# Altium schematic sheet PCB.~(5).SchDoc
size A2
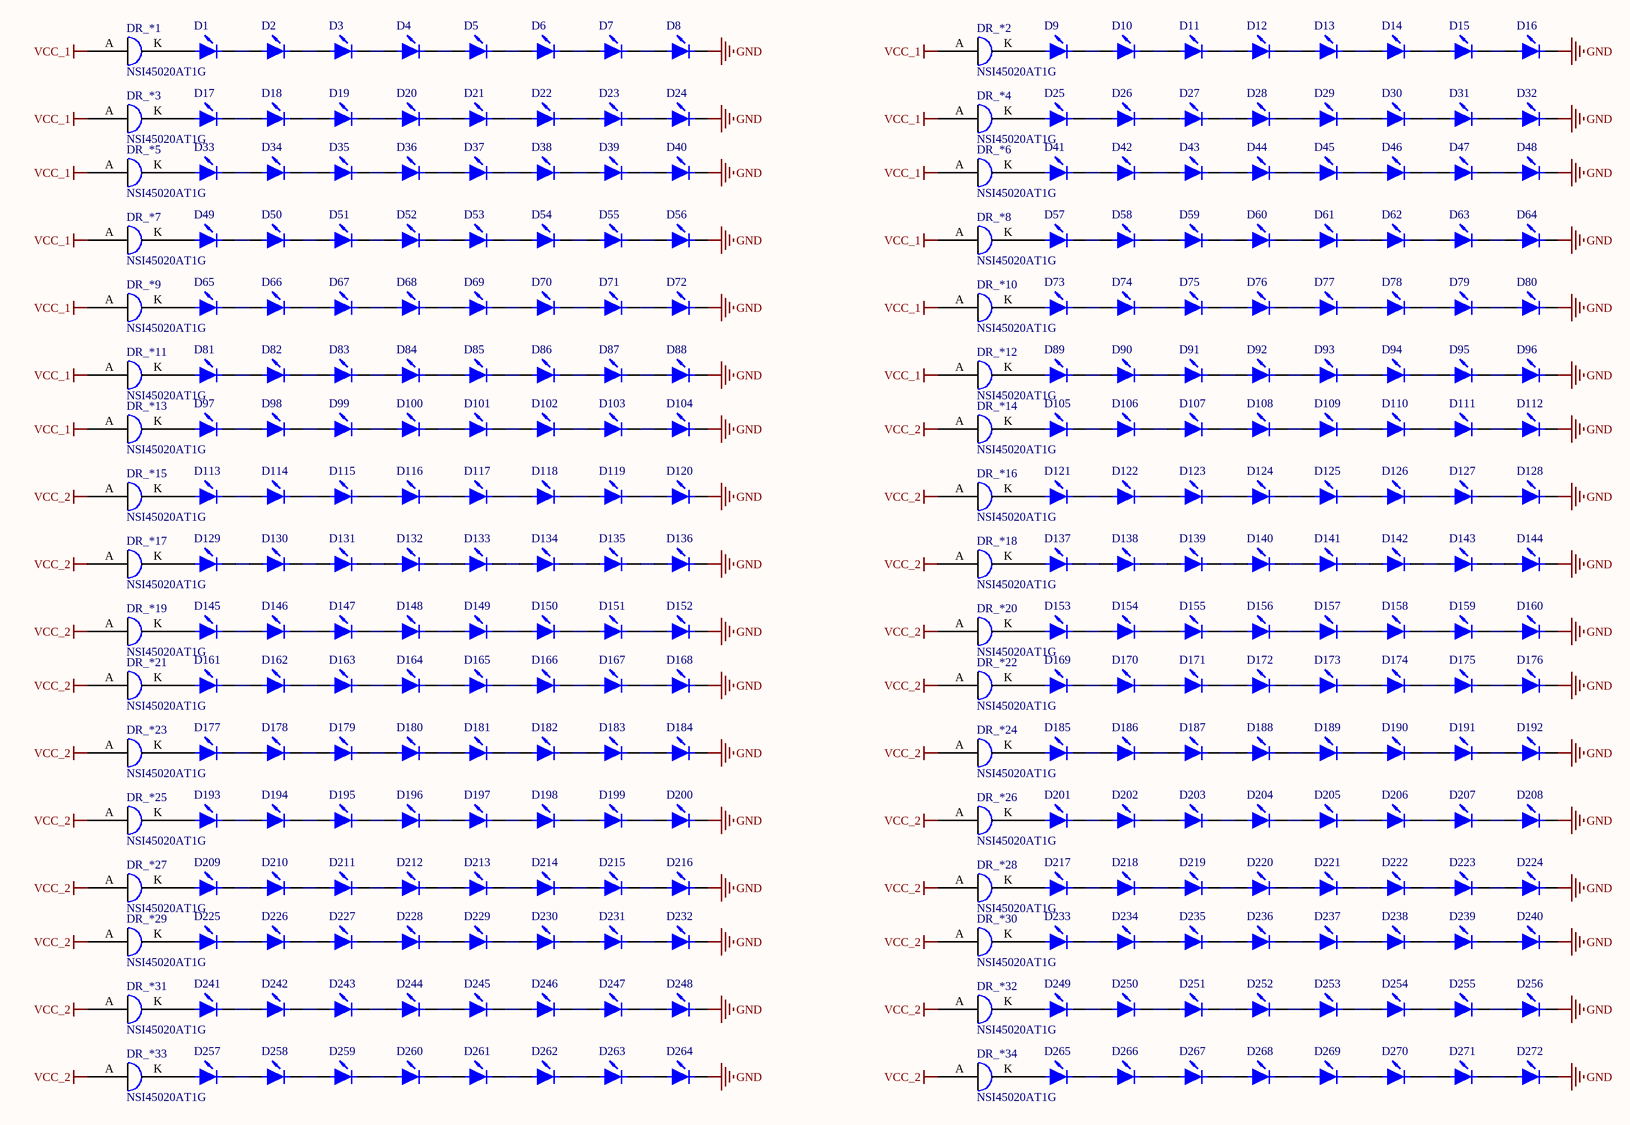
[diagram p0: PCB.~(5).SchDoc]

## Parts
D1  LED0  [UV_LED]  (value not drawn)
D2  LED0  [UV_LED]  (value not drawn)
D3  LED0  [UV_LED]  (value not drawn)
D4  LED0  [UV_LED]  (value not drawn)
D5  LED0  [UV_LED]  (value not drawn)
D6  LED0  [UV_LED]  (value not drawn)
D7  LED0  [UV_LED]  (value not drawn)
D8  LED0  [UV_LED]  (value not drawn)
D9  LED0  [UV_LED]  (value not drawn)
D10  LED0  [UV_LED]  (value not drawn)
D11  LED0  [UV_LED]  (value not drawn)
D12  LED0  [UV_LED]  (value not drawn)
D13  LED0  [UV_LED]  (value not drawn)
D14  LED0  [UV_LED]  (value not drawn)
D15  LED0  [UV_LED]  (value not drawn)
D16  LED0  [UV_LED]  (value not drawn)
D17  LED0  [UV_LED]  (value not drawn)
D18  LED0  [UV_LED]  (value not drawn)
D19  LED0  [UV_LED]  (value not drawn)
D20  LED0  [UV_LED]  (value not drawn)
D21  LED0  [UV_LED]  (value not drawn)
D22  LED0  [UV_LED]  (value not drawn)
D23  LED0  [UV_LED]  (value not drawn)
D24  LED0  [UV_LED]  (value not drawn)
D25  LED0  [UV_LED]  (value not drawn)
D26  LED0  [UV_LED]  (value not drawn)
D27  LED0  [UV_LED]  (value not drawn)
D28  LED0  [UV_LED]  (value not drawn)
D29  LED0  [UV_LED]  (value not drawn)
D30  LED0  [UV_LED]  (value not drawn)
D31  LED0  [UV_LED]  (value not drawn)
D32  LED0  [UV_LED]  (value not drawn)
D33  LED0  [UV_LED]  (value not drawn)
D34  LED0  [UV_LED]  (value not drawn)
D35  LED0  [UV_LED]  (value not drawn)
D36  LED0  [UV_LED]  (value not drawn)
D37  LED0  [UV_LED]  (value not drawn)
D38  LED0  [UV_LED]  (value not drawn)
D39  LED0  [UV_LED]  (value not drawn)
D40  LED0  [UV_LED]  (value not drawn)
D41  LED0  [UV_LED]  (value not drawn)
D42  LED0  [UV_LED]  (value not drawn)
D43  LED0  [UV_LED]  (value not drawn)
D44  LED0  [UV_LED]  (value not drawn)
D45  LED0  [UV_LED]  (value not drawn)
D46  LED0  [UV_LED]  (value not drawn)
D47  LED0  [UV_LED]  (value not drawn)
D48  LED0  [UV_LED]  (value not drawn)
D49  LED0  [UV_LED]  (value not drawn)
D50  LED0  [UV_LED]  (value not drawn)
D51  LED0  [UV_LED]  (value not drawn)
D52  LED0  [UV_LED]  (value not drawn)
D53  LED0  [UV_LED]  (value not drawn)
D54  LED0  [UV_LED]  (value not drawn)
D55  LED0  [UV_LED]  (value not drawn)
D56  LED0  [UV_LED]  (value not drawn)
D57  LED0  [UV_LED]  (value not drawn)
D58  LED0  [UV_LED]  (value not drawn)
D59  LED0  [UV_LED]  (value not drawn)
D60  LED0  [UV_LED]  (value not drawn)
D61  LED0  [UV_LED]  (value not drawn)
D62  LED0  [UV_LED]  (value not drawn)
D63  LED0  [UV_LED]  (value not drawn)
D64  LED0  [UV_LED]  (value not drawn)
D65  LED0  [UV_LED]  (value not drawn)
D66  LED0  [UV_LED]  (value not drawn)
D67  LED0  [UV_LED]  (value not drawn)
D68  LED0  [UV_LED]  (value not drawn)
D69  LED0  [UV_LED]  (value not drawn)
D70  LED0  [UV_LED]  (value not drawn)
D71  LED0  [UV_LED]  (value not drawn)
D72  LED0  [UV_LED]  (value not drawn)
D73  LED0  [UV_LED]  (value not drawn)
D74  LED0  [UV_LED]  (value not drawn)
D75  LED0  [UV_LED]  (value not drawn)
D76  LED0  [UV_LED]  (value not drawn)
D77  LED0  [UV_LED]  (value not drawn)
D78  LED0  [UV_LED]  (value not drawn)
D79  LED0  [UV_LED]  (value not drawn)
D80  LED0  [UV_LED]  (value not drawn)
D81  LED0  [UV_LED]  (value not drawn)
D82  LED0  [UV_LED]  (value not drawn)
D83  LED0  [UV_LED]  (value not drawn)
D84  LED0  [UV_LED]  (value not drawn)
D85  LED0  [UV_LED]  (value not drawn)
D86  LED0  [UV_LED]  (value not drawn)
D87  LED0  [UV_LED]  (value not drawn)
D88  LED0  [UV_LED]  (value not drawn)
D89  LED0  [UV_LED]  (value not drawn)
D90  LED0  [UV_LED]  (value not drawn)
D91  LED0  [UV_LED]  (value not drawn)
D92  LED0  [UV_LED]  (value not drawn)
D93  LED0  [UV_LED]  (value not drawn)
D94  LED0  [UV_LED]  (value not drawn)
D95  LED0  [UV_LED]  (value not drawn)
D96  LED0  [UV_LED]  (value not drawn)
D97  LED0  [UV_LED]  (value not drawn)
D98  LED0  [UV_LED]  (value not drawn)
D99  LED0  [UV_LED]  (value not drawn)
D100  LED0  [UV_LED]  (value not drawn)
D101  LED0  [UV_LED]  (value not drawn)
D102  LED0  [UV_LED]  (value not drawn)
D103  LED0  [UV_LED]  (value not drawn)
D104  LED0  [UV_LED]  (value not drawn)
D105  LED0  [UV_LED]  (value not drawn)
D106  LED0  [UV_LED]  (value not drawn)
D107  LED0  [UV_LED]  (value not drawn)
D108  LED0  [UV_LED]  (value not drawn)
D109  LED0  [UV_LED]  (value not drawn)
D110  LED0  [UV_LED]  (value not drawn)
D111  LED0  [UV_LED]  (value not drawn)
D112  LED0  [UV_LED]  (value not drawn)
D113  LED0  [UV_LED]  (value not drawn)
D114  LED0  [UV_LED]  (value not drawn)
D115  LED0  [UV_LED]  (value not drawn)
D116  LED0  [UV_LED]  (value not drawn)
D117  LED0  [UV_LED]  (value not drawn)
D118  LED0  [UV_LED]  (value not drawn)
D119  LED0  [UV_LED]  (value not drawn)
D120  LED0  [UV_LED]  (value not drawn)
D121  LED0  [UV_LED]  (value not drawn)
D122  LED0  [UV_LED]  (value not drawn)
D123  LED0  [UV_LED]  (value not drawn)
D124  LED0  [UV_LED]  (value not drawn)
D125  LED0  [UV_LED]  (value not drawn)
D126  LED0  [UV_LED]  (value not drawn)
D127  LED0  [UV_LED]  (value not drawn)
D128  LED0  [UV_LED]  (value not drawn)
D129  LED0  [UV_LED]  (value not drawn)
D130  LED0  [UV_LED]  (value not drawn)
D131  LED0  [UV_LED]  (value not drawn)
D132  LED0  [UV_LED]  (value not drawn)
D133  LED0  [UV_LED]  (value not drawn)
D134  LED0  [UV_LED]  (value not drawn)
D135  LED0  [UV_LED]  (value not drawn)
D136  LED0  [UV_LED]  (value not drawn)
D137  LED0  [UV_LED]  (value not drawn)
D138  LED0  [UV_LED]  (value not drawn)
D139  LED0  [UV_LED]  (value not drawn)
D140  LED0  [UV_LED]  (value not drawn)
D141  LED0  [UV_LED]  (value not drawn)
D142  LED0  [UV_LED]  (value not drawn)
D143  LED0  [UV_LED]  (value not drawn)
D144  LED0  [UV_LED]  (value not drawn)
D145  LED0  [UV_LED]  (value not drawn)
D146  LED0  [UV_LED]  (value not drawn)
D147  LED0  [UV_LED]  (value not drawn)
D148  LED0  [UV_LED]  (value not drawn)
D149  LED0  [UV_LED]  (value not drawn)
D150  LED0  [UV_LED]  (value not drawn)
D151  LED0  [UV_LED]  (value not drawn)
D152  LED0  [UV_LED]  (value not drawn)
D153  LED0  [UV_LED]  (value not drawn)
D154  LED0  [UV_LED]  (value not drawn)
D155  LED0  [UV_LED]  (value not drawn)
D156  LED0  [UV_LED]  (value not drawn)
D157  LED0  [UV_LED]  (value not drawn)
D158  LED0  [UV_LED]  (value not drawn)
D159  LED0  [UV_LED]  (value not drawn)
D160  LED0  [UV_LED]  (value not drawn)
D161  LED0  [UV_LED]  (value not drawn)
D162  LED0  [UV_LED]  (value not drawn)
D163  LED0  [UV_LED]  (value not drawn)
D164  LED0  [UV_LED]  (value not drawn)
D165  LED0  [UV_LED]  (value not drawn)
D166  LED0  [UV_LED]  (value not drawn)
D167  LED0  [UV_LED]  (value not drawn)
D168  LED0  [UV_LED]  (value not drawn)
D169  LED0  [UV_LED]  (value not drawn)
D170  LED0  [UV_LED]  (value not drawn)
D171  LED0  [UV_LED]  (value not drawn)
D172  LED0  [UV_LED]  (value not drawn)
D173  LED0  [UV_LED]  (value not drawn)
D174  LED0  [UV_LED]  (value not drawn)
D175  LED0  [UV_LED]  (value not drawn)
D176  LED0  [UV_LED]  (value not drawn)
D177  LED0  [UV_LED]  (value not drawn)
D178  LED0  [UV_LED]  (value not drawn)
D179  LED0  [UV_LED]  (value not drawn)
D180  LED0  [UV_LED]  (value not drawn)
D181  LED0  [UV_LED]  (value not drawn)
D182  LED0  [UV_LED]  (value not drawn)
D183  LED0  [UV_LED]  (value not drawn)
D184  LED0  [UV_LED]  (value not drawn)
D185  LED0  [UV_LED]  (value not drawn)
D186  LED0  [UV_LED]  (value not drawn)
D187  LED0  [UV_LED]  (value not drawn)
D188  LED0  [UV_LED]  (value not drawn)
D189  LED0  [UV_LED]  (value not drawn)
D190  LED0  [UV_LED]  (value not drawn)
D191  LED0  [UV_LED]  (value not drawn)
D192  LED0  [UV_LED]  (value not drawn)
D193  LED0  [UV_LED]  (value not drawn)
D194  LED0  [UV_LED]  (value not drawn)
D195  LED0  [UV_LED]  (value not drawn)
D196  LED0  [UV_LED]  (value not drawn)
D197  LED0  [UV_LED]  (value not drawn)
D198  LED0  [UV_LED]  (value not drawn)
D199  LED0  [UV_LED]  (value not drawn)
D200  LED0  [UV_LED]  (value not drawn)
D201  LED0  [UV_LED]  (value not drawn)
D202  LED0  [UV_LED]  (value not drawn)
D203  LED0  [UV_LED]  (value not drawn)
D204  LED0  [UV_LED]  (value not drawn)
D205  LED0  [UV_LED]  (value not drawn)
D206  LED0  [UV_LED]  (value not drawn)
D207  LED0  [UV_LED]  (value not drawn)
D208  LED0  [UV_LED]  (value not drawn)
D209  LED0  [UV_LED]  (value not drawn)
D210  LED0  [UV_LED]  (value not drawn)
D211  LED0  [UV_LED]  (value not drawn)
D212  LED0  [UV_LED]  (value not drawn)
D213  LED0  [UV_LED]  (value not drawn)
D214  LED0  [UV_LED]  (value not drawn)
D215  LED0  [UV_LED]  (value not drawn)
D216  LED0  [UV_LED]  (value not drawn)
D217  LED0  [UV_LED]  (value not drawn)
D218  LED0  [UV_LED]  (value not drawn)
D219  LED0  [UV_LED]  (value not drawn)
D220  LED0  [UV_LED]  (value not drawn)
D221  LED0  [UV_LED]  (value not drawn)
D222  LED0  [UV_LED]  (value not drawn)
D223  LED0  [UV_LED]  (value not drawn)
D224  LED0  [UV_LED]  (value not drawn)
D225  LED0  [UV_LED]  (value not drawn)
D226  LED0  [UV_LED]  (value not drawn)
D227  LED0  [UV_LED]  (value not drawn)
D228  LED0  [UV_LED]  (value not drawn)
D229  LED0  [UV_LED]  (value not drawn)
D230  LED0  [UV_LED]  (value not drawn)
D231  LED0  [UV_LED]  (value not drawn)
D232  LED0  [UV_LED]  (value not drawn)
D233  LED0  [UV_LED]  (value not drawn)
D234  LED0  [UV_LED]  (value not drawn)
D235  LED0  [UV_LED]  (value not drawn)
D236  LED0  [UV_LED]  (value not drawn)
D237  LED0  [UV_LED]  (value not drawn)
D238  LED0  [UV_LED]  (value not drawn)
D239  LED0  [UV_LED]  (value not drawn)
D240  LED0  [UV_LED]  (value not drawn)
D241  LED0  [UV_LED]  (value not drawn)
D242  LED0  [UV_LED]  (value not drawn)
D243  LED0  [UV_LED]  (value not drawn)
D244  LED0  [UV_LED]  (value not drawn)
D245  LED0  [UV_LED]  (value not drawn)
D246  LED0  [UV_LED]  (value not drawn)
D247  LED0  [UV_LED]  (value not drawn)
D248  LED0  [UV_LED]  (value not drawn)
D249  LED0  [UV_LED]  (value not drawn)
D250  LED0  [UV_LED]  (value not drawn)
D251  LED0  [UV_LED]  (value not drawn)
D252  LED0  [UV_LED]  (value not drawn)
D253  LED0  [UV_LED]  (value not drawn)
D254  LED0  [UV_LED]  (value not drawn)
D255  LED0  [UV_LED]  (value not drawn)
D256  LED0  [UV_LED]  (value not drawn)
D257  LED0  [UV_LED]  (value not drawn)
D258  LED0  [UV_LED]  (value not drawn)
D259  LED0  [UV_LED]  (value not drawn)
D260  LED0  [UV_LED]  (value not drawn)
D261  LED0  [UV_LED]  (value not drawn)
D262  LED0  [UV_LED]  (value not drawn)
D263  LED0  [UV_LED]  (value not drawn)
D264  LED0  [UV_LED]  (value not drawn)
D265  LED0  [UV_LED]  (value not drawn)
D266  LED0  [UV_LED]  (value not drawn)
D267  LED0  [UV_LED]  (value not drawn)
D268  LED0  [UV_LED]  (value not drawn)
D269  LED0  [UV_LED]  (value not drawn)
D270  LED0  [UV_LED]  (value not drawn)
D271  LED0  [UV_LED]  (value not drawn)
D272  LED0  [UV_LED]  (value not drawn)
DR_*1  NSI45020AT1G  [NSI45020AT1G]
DR_*2  NSI45020AT1G  [NSI45020AT1G]
DR_*3  NSI45020AT1G  [NSI45020AT1G]
DR_*4  NSI45020AT1G  [NSI45020AT1G]
DR_*5  NSI45020AT1G  [NSI45020AT1G]
DR_*6  NSI45020AT1G  [NSI45020AT1G]
DR_*7  NSI45020AT1G  [NSI45020AT1G]
DR_*8  NSI45020AT1G  [NSI45020AT1G]
DR_*9  NSI45020AT1G  [NSI45020AT1G]
DR_*10  NSI45020AT1G  [NSI45020AT1G]
DR_*11  NSI45020AT1G  [NSI45020AT1G]
DR_*12  NSI45020AT1G  [NSI45020AT1G]
DR_*13  NSI45020AT1G  [NSI45020AT1G]
DR_*14  NSI45020AT1G  [NSI45020AT1G]
DR_*15  NSI45020AT1G  [NSI45020AT1G]
DR_*16  NSI45020AT1G  [NSI45020AT1G]
DR_*17  NSI45020AT1G  [NSI45020AT1G]
DR_*18  NSI45020AT1G  [NSI45020AT1G]
DR_*19  NSI45020AT1G  [NSI45020AT1G]
DR_*20  NSI45020AT1G  [NSI45020AT1G]
DR_*21  NSI45020AT1G  [NSI45020AT1G]
DR_*22  NSI45020AT1G  [NSI45020AT1G]
DR_*23  NSI45020AT1G  [NSI45020AT1G]
DR_*24  NSI45020AT1G  [NSI45020AT1G]
DR_*25  NSI45020AT1G  [NSI45020AT1G]
DR_*26  NSI45020AT1G  [NSI45020AT1G]
DR_*27  NSI45020AT1G  [NSI45020AT1G]
DR_*28  NSI45020AT1G  [NSI45020AT1G]
DR_*29  NSI45020AT1G  [NSI45020AT1G]
DR_*30  NSI45020AT1G  [NSI45020AT1G]
DR_*31  NSI45020AT1G  [NSI45020AT1G]
DR_*32  NSI45020AT1G  [NSI45020AT1G]
DR_*33  NSI45020AT1G  [NSI45020AT1G]
DR_*34  NSI45020AT1G  [NSI45020AT1G]

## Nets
GND: D8.2(K) D16.2(K) D24.2(K) D32.2(K) D40.2(K) D48.2(K) D56.2(K) D64.2(K) D72.2(K) D80.2(K) D88.2(K) D96.2(K) D104.2(K) D112.2(K) D120.2(K) D128.2(K) D136.2(K) D144.2(K) D152.2(K) D160.2(K) D168.2(K) D176.2(K) D184.2(K) D192.2(K) D200.2(K) D208.2(K) D216.2(K) D224.2(K) D232.2(K) D240.2(K) D248.2(K) D256.2(K) D264.2(K) D272.2(K)
VCC_1: DR_*1.A DR_*2.A DR_*3.A DR_*4.A DR_*5.A DR_*6.A DR_*7.A DR_*8.A DR_*9.A DR_*10.A DR_*11.A DR_*12.A DR_*13.A
VCC_2: DR_*14.A DR_*15.A DR_*16.A DR_*17.A DR_*18.A DR_*19.A DR_*20.A DR_*21.A DR_*22.A DR_*23.A DR_*24.A DR_*25.A DR_*26.A DR_*27.A DR_*28.A DR_*29.A DR_*30.A DR_*31.A DR_*32.A DR_*33.A DR_*34.A
NetD1_1: D1.1(A) DR_*1.K
NetD1_2: D1.2(K) D2.1(A)
NetD2_2: D2.2(K) D3.1(A)
NetD3_2: D3.2(K) D4.1(A)
NetD4_2: D4.2(K) D5.1(A)
NetD5_2: D5.2(K) D6.1(A)
NetD6_2: D6.2(K) D7.1(A)
NetD7_2: D7.2(K) D8.1(A)
NetD9_1: D9.1(A) DR_*2.K
NetD9_2: D9.2(K) D10.1(A)
NetD10_2: D10.2(K) D11.1(A)
NetD11_2: D11.2(K) D12.1(A)
NetD12_2: D12.2(K) D13.1(A)
NetD13_2: D13.2(K) D14.1(A)
NetD14_2: D14.2(K) D15.1(A)
NetD15_2: D15.2(K) D16.1(A)
NetD17_1: D17.1(A) DR_*3.K
NetD17_2: D17.2(K) D18.1(A)
NetD18_2: D18.2(K) D19.1(A)
NetD19_2: D19.2(K) D20.1(A)
NetD20_2: D20.2(K) D21.1(A)
NetD21_2: D21.2(K) D22.1(A)
NetD22_2: D22.2(K) D23.1(A)
NetD23_2: D23.2(K) D24.1(A)
NetD25_1: D25.1(A) DR_*4.K
NetD25_2: D25.2(K) D26.1(A)
NetD26_2: D26.2(K) D27.1(A)
NetD27_2: D27.2(K) D28.1(A)
NetD28_2: D28.2(K) D29.1(A)
NetD29_2: D29.2(K) D30.1(A)
NetD30_2: D30.2(K) D31.1(A)
NetD31_2: D31.2(K) D32.1(A)
NetD33_1: D33.1(A) DR_*5.K
NetD33_2: D33.2(K) D34.1(A)
NetD34_2: D34.2(K) D35.1(A)
NetD35_2: D35.2(K) D36.1(A)
NetD36_2: D36.2(K) D37.1(A)
NetD37_2: D37.2(K) D38.1(A)
NetD38_2: D38.2(K) D39.1(A)
NetD39_2: D39.2(K) D40.1(A)
NetD41_1: D41.1(A) DR_*6.K
NetD41_2: D41.2(K) D42.1(A)
NetD42_2: D42.2(K) D43.1(A)
NetD43_2: D43.2(K) D44.1(A)
NetD44_2: D44.2(K) D45.1(A)
NetD45_2: D45.2(K) D46.1(A)
NetD46_2: D46.2(K) D47.1(A)
NetD47_2: D47.2(K) D48.1(A)
NetD49_1: D49.1(A) DR_*7.K
NetD49_2: D49.2(K) D50.1(A)
NetD50_2: D50.2(K) D51.1(A)
NetD51_2: D51.2(K) D52.1(A)
NetD52_2: D52.2(K) D53.1(A)
NetD53_2: D53.2(K) D54.1(A)
NetD54_2: D54.2(K) D55.1(A)
NetD55_2: D55.2(K) D56.1(A)
NetD57_1: D57.1(A) DR_*8.K
NetD57_2: D57.2(K) D58.1(A)
NetD58_2: D58.2(K) D59.1(A)
NetD59_2: D59.2(K) D60.1(A)
NetD60_2: D60.2(K) D61.1(A)
NetD61_2: D61.2(K) D62.1(A)
NetD62_2: D62.2(K) D63.1(A)
NetD63_2: D63.2(K) D64.1(A)
NetD65_1: D65.1(A) DR_*9.K
NetD65_2: D65.2(K) D66.1(A)
NetD66_2: D66.2(K) D67.1(A)
NetD67_2: D67.2(K) D68.1(A)
NetD68_2: D68.2(K) D69.1(A)
NetD69_2: D69.2(K) D70.1(A)
NetD70_2: D70.2(K) D71.1(A)
NetD71_2: D71.2(K) D72.1(A)
NetD73_1: D73.1(A) DR_*10.K
NetD73_2: D73.2(K) D74.1(A)
NetD74_2: D74.2(K) D75.1(A)
NetD75_2: D75.2(K) D76.1(A)
NetD76_2: D76.2(K) D77.1(A)
NetD77_2: D77.2(K) D78.1(A)
NetD78_2: D78.2(K) D79.1(A)
NetD79_2: D79.2(K) D80.1(A)
NetD81_1: D81.1(A) DR_*11.K
NetD81_2: D81.2(K) D82.1(A)
NetD82_2: D82.2(K) D83.1(A)
NetD83_2: D83.2(K) D84.1(A)
NetD84_2: D84.2(K) D85.1(A)
NetD85_2: D85.2(K) D86.1(A)
NetD86_2: D86.2(K) D87.1(A)
NetD87_2: D87.2(K) D88.1(A)
NetD89_1: D89.1(A) DR_*12.K
NetD89_2: D89.2(K) D90.1(A)
NetD90_2: D90.2(K) D91.1(A)
NetD91_2: D91.2(K) D92.1(A)
NetD92_2: D92.2(K) D93.1(A)
NetD93_2: D93.2(K) D94.1(A)
NetD94_2: D94.2(K) D95.1(A)
NetD95_2: D95.2(K) D96.1(A)
NetD97_1: D97.1(A) DR_*13.K
NetD97_2: D97.2(K) D98.1(A)
NetD98_2: D98.2(K) D99.1(A)
NetD99_2: D99.2(K) D100.1(A)
NetD100_2: D100.2(K) D101.1(A)
NetD101_2: D101.2(K) D102.1(A)
NetD102_2: D102.2(K) D103.1(A)
NetD103_2: D103.2(K) D104.1(A)
NetD105_1: D105.1(A) DR_*14.K
NetD105_2: D105.2(K) D106.1(A)
NetD106_2: D106.2(K) D107.1(A)
NetD107_2: D107.2(K) D108.1(A)
NetD108_2: D108.2(K) D109.1(A)
NetD109_2: D109.2(K) D110.1(A)
NetD110_2: D110.2(K) D111.1(A)
NetD111_2: D111.2(K) D112.1(A)
NetD113_1: D113.1(A) DR_*15.K
NetD113_2: D113.2(K) D114.1(A)
NetD114_2: D114.2(K) D115.1(A)
NetD115_2: D115.2(K) D116.1(A)
NetD116_2: D116.2(K) D117.1(A)
NetD117_2: D117.2(K) D118.1(A)
NetD118_2: D118.2(K) D119.1(A)
NetD119_2: D119.2(K) D120.1(A)
NetD121_1: D121.1(A) DR_*16.K
NetD121_2: D121.2(K) D122.1(A)
NetD122_2: D122.2(K) D123.1(A)
NetD123_2: D123.2(K) D124.1(A)
NetD124_2: D124.2(K) D125.1(A)
NetD125_2: D125.2(K) D126.1(A)
NetD126_2: D126.2(K) D127.1(A)
NetD127_2: D127.2(K) D128.1(A)
NetD129_1: D129.1(A) DR_*17.K
NetD129_2: D129.2(K) D130.1(A)
NetD130_2: D130.2(K) D131.1(A)
NetD131_2: D131.2(K) D132.1(A)
NetD132_2: D132.2(K) D133.1(A)
NetD133_2: D133.2(K) D134.1(A)
NetD134_2: D134.2(K) D135.1(A)
NetD135_2: D135.2(K) D136.1(A)
NetD137_1: D137.1(A) DR_*18.K
NetD137_2: D137.2(K) D138.1(A)
NetD138_2: D138.2(K) D139.1(A)
NetD139_2: D139.2(K) D140.1(A)
NetD140_2: D140.2(K) D141.1(A)
NetD141_2: D141.2(K) D142.1(A)
NetD142_2: D142.2(K) D143.1(A)
NetD143_2: D143.2(K) D144.1(A)
NetD145_1: D145.1(A) DR_*19.K
NetD145_2: D145.2(K) D146.1(A)
NetD146_2: D146.2(K) D147.1(A)
NetD147_2: D147.2(K) D148.1(A)
NetD148_2: D148.2(K) D149.1(A)
NetD149_2: D149.2(K) D150.1(A)
NetD150_2: D150.2(K) D151.1(A)
NetD151_2: D151.2(K) D152.1(A)
NetD153_1: D153.1(A) DR_*20.K
NetD153_2: D153.2(K) D154.1(A)
NetD154_2: D154.2(K) D155.1(A)
NetD155_2: D155.2(K) D156.1(A)
NetD156_2: D156.2(K) D157.1(A)
NetD157_2: D157.2(K) D158.1(A)
NetD158_2: D158.2(K) D159.1(A)
NetD159_2: D159.2(K) D160.1(A)
NetD161_1: D161.1(A) DR_*21.K
NetD161_2: D161.2(K) D162.1(A)
NetD162_2: D162.2(K) D163.1(A)
NetD163_2: D163.2(K) D164.1(A)
NetD164_2: D164.2(K) D165.1(A)
NetD165_2: D165.2(K) D166.1(A)
NetD166_2: D166.2(K) D167.1(A)
NetD167_2: D167.2(K) D168.1(A)
NetD169_1: D169.1(A) DR_*22.K
NetD169_2: D169.2(K) D170.1(A)
NetD170_2: D170.2(K) D171.1(A)
NetD171_2: D171.2(K) D172.1(A)
NetD172_2: D172.2(K) D173.1(A)
NetD173_2: D173.2(K) D174.1(A)
NetD174_2: D174.2(K) D175.1(A)
NetD175_2: D175.2(K) D176.1(A)
NetD177_1: D177.1(A) DR_*23.K
NetD177_2: D177.2(K) D178.1(A)
NetD178_2: D178.2(K) D179.1(A)
NetD179_2: D179.2(K) D180.1(A)
NetD180_2: D180.2(K) D181.1(A)
NetD181_2: D181.2(K) D182.1(A)
NetD182_2: D182.2(K) D183.1(A)
NetD183_2: D183.2(K) D184.1(A)
NetD185_1: D185.1(A) DR_*24.K
NetD185_2: D185.2(K) D186.1(A)
NetD186_2: D186.2(K) D187.1(A)
NetD187_2: D187.2(K) D188.1(A)
NetD188_2: D188.2(K) D189.1(A)
NetD189_2: D189.2(K) D190.1(A)
NetD190_2: D190.2(K) D191.1(A)
NetD191_2: D191.2(K) D192.1(A)
NetD193_1: D193.1(A) DR_*25.K
NetD193_2: D193.2(K) D194.1(A)
NetD194_2: D194.2(K) D195.1(A)
NetD195_2: D195.2(K) D196.1(A)
NetD196_2: D196.2(K) D197.1(A)
NetD197_2: D197.2(K) D198.1(A)
NetD198_2: D198.2(K) D199.1(A)
NetD199_2: D199.2(K) D200.1(A)
NetD201_1: D201.1(A) DR_*26.K
NetD201_2: D201.2(K) D202.1(A)
NetD202_2: D202.2(K) D203.1(A)
NetD203_2: D203.2(K) D204.1(A)
NetD204_2: D204.2(K) D205.1(A)
NetD205_2: D205.2(K) D206.1(A)
NetD206_2: D206.2(K) D207.1(A)
NetD207_2: D207.2(K) D208.1(A)
NetD209_1: D209.1(A) DR_*27.K
NetD209_2: D209.2(K) D210.1(A)
NetD210_2: D210.2(K) D211.1(A)
NetD211_2: D211.2(K) D212.1(A)
NetD212_2: D212.2(K) D213.1(A)
NetD213_2: D213.2(K) D214.1(A)
NetD214_2: D214.2(K) D215.1(A)
NetD215_2: D215.2(K) D216.1(A)
NetD217_1: D217.1(A) DR_*28.K
NetD217_2: D217.2(K) D218.1(A)
NetD218_2: D218.2(K) D219.1(A)
NetD219_2: D219.2(K) D220.1(A)
NetD220_2: D220.2(K) D221.1(A)
NetD221_2: D221.2(K) D222.1(A)
NetD222_2: D222.2(K) D223.1(A)
NetD223_2: D223.2(K) D224.1(A)
NetD225_1: D225.1(A) DR_*29.K
NetD225_2: D225.2(K) D226.1(A)
NetD226_2: D226.2(K) D227.1(A)
NetD227_2: D227.2(K) D228.1(A)
NetD228_2: D228.2(K) D229.1(A)
NetD229_2: D229.2(K) D230.1(A)
NetD230_2: D230.2(K) D231.1(A)
NetD231_2: D231.2(K) D232.1(A)
NetD233_1: D233.1(A) DR_*30.K
NetD233_2: D233.2(K) D234.1(A)
NetD234_2: D234.2(K) D235.1(A)
NetD235_2: D235.2(K) D236.1(A)
NetD236_2: D236.2(K) D237.1(A)
NetD237_2: D237.2(K) D238.1(A)
NetD238_2: D238.2(K) D239.1(A)
NetD239_2: D239.2(K) D240.1(A)
NetD241_1: D241.1(A) DR_*31.K
NetD241_2: D241.2(K) D242.1(A)
NetD242_2: D242.2(K) D243.1(A)
NetD243_2: D243.2(K) D244.1(A)
NetD244_2: D244.2(K) D245.1(A)
NetD245_2: D245.2(K) D246.1(A)
NetD246_2: D246.2(K) D247.1(A)
NetD247_2: D247.2(K) D248.1(A)
NetD249_1: D249.1(A) DR_*32.K
NetD249_2: D249.2(K) D250.1(A)
NetD250_2: D250.2(K) D251.1(A)
NetD251_2: D251.2(K) D252.1(A)
NetD252_2: D252.2(K) D253.1(A)
NetD253_2: D253.2(K) D254.1(A)
NetD254_2: D254.2(K) D255.1(A)
NetD255_2: D255.2(K) D256.1(A)
NetD257_1: D257.1(A) DR_*33.K
NetD257_2: D257.2(K) D258.1(A)
NetD258_2: D258.2(K) D259.1(A)
NetD259_2: D259.2(K) D260.1(A)
NetD260_2: D260.2(K) D261.1(A)
NetD261_2: D261.2(K) D262.1(A)
NetD262_2: D262.2(K) D263.1(A)
NetD263_2: D263.2(K) D264.1(A)
NetD265_1: D265.1(A) DR_*34.K
NetD265_2: D265.2(K) D266.1(A)
NetD266_2: D266.2(K) D267.1(A)
NetD267_2: D267.2(K) D268.1(A)
NetD268_2: D268.2(K) D269.1(A)
NetD269_2: D269.2(K) D270.1(A)
NetD270_2: D270.2(K) D271.1(A)
NetD271_2: D271.2(K) D272.1(A)

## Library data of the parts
D1-D272 = LED0: Typical INFRARED GaAs LED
